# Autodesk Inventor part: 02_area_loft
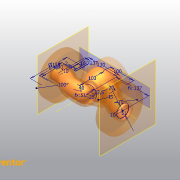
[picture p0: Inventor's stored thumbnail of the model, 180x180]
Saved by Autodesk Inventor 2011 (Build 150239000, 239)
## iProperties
Created: 2002-07
Part Number: 02_area_loft
Document SubType Name: Modeling
Designer: Lieven Grauls
Project: Valve Techcamp 2008
Density: 1 g/cm^3
Company: Autodesk
Control State: 0
Master: False
Checked Out: False
Shininess: 64.0
Length Units: 11269
Angle Units: 11279
Time Units: 11290
Mass Units: 11283
Length Display Precision: 3
Angle Display Precision: 2
Density: 0.0
Volumn: 0.0
Area: 0.0
PropertySet Name: Model Information
Author: Lieven Grauls
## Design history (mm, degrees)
sketch "Sketch2"
  geometry: L1 (-137, 0)-(-127, 0); L2 (137, 0)-(127, 0); L3 (45.866, 33.5)-(25.866, 33.5); L4 (-50, 103)-(50, 103); L5 (0, -142.6)-(0, 155.6) reference; L6 (-47.156, -25)-(0, -25); A1 r 100 centre (-127, -100) between (-69.969, -17.857) and (-127, 0); A2 r 40 centre (-47.156, 15) between (-69.969, -17.857) and (-47.156, -25); A3 r 70 centre (127, 70) between (77.614, 20.391) and (127, 0); A4 r 45 centre (45.866, -11.5) between (77.614, 20.391) and (45.866, 33.5); 4 further points
  constraints: 10 end point, 8 point on circle, 6 tangent, 4 centre point, 3 horizontal, 2 horizontal alignment, 2 perpendicular, 2 point on line, 1 midpoint, 1 other
  dimensions: "d8" = 137 distance of L1.start point (0, 0); "d9" = 100 radius of A1; "d10" = 40 radius of A2; "d15" = 137 distance of L2.start point (0, 0) (= d8); "d16" = 70 radius of A3; "d61" = 33.5 distance of the line from the sketch origin of L3; "d63" = 45 radius of A4; "d102" = 10 distance of L1.start L1.end; "d103" = 10 distance of L2.start L2.end; "d182" = 20 distance of L3.start L3.end; "d220" = 103 distance of the line from the sketch origin of L4; "d221" = 100 distance of L4.start L4.end; "d249" = 25 distance of the line from the sketch origin of L6
workplane "Work Plane6"
workplane "Work Plane2"
workplane "Work Plane1"
sketch "Sketch5"
  geometry: C1 r 25.5 at (0, 0); 1 further point
  constraints: 1 centre point, 1 coincident
  dimensions: "d24" = 51 diameter of C1
sketch "Sketch6"
  geometry: C1 r 25.5 at (0, 0); 1 further point
  constraints: 1 centre point, 1 coincident
  dimensions: "d25" = 51 diameter of C1
sketch "Sketch11"
  geometry: C1 r 25.5 at (0, 0); 1 further point
  constraints: 1 centre point, 1 coincident
  dimensions: "d104" = 51 diameter of C1 (= d24)
sketch "Sketch7"
  geometry: L1 (0, -22.6)-(0, 135.6) reference; L2 (-32.5, 103)-(-32.5, 74); L3 (-32.5, 74)-(-45.093, 69.417); L4 (-32.5, 8)-(0, 8); L5 (0, 103)-(-32.5, 103); L6 (-46.873, 22.579)-(-39.053, 11.411); L7 (-183.58, 0)-(30.597, 0) reference; A1 r 18 centre (-38.936, 52.502) between (-45.093, 69.417) and (-56.906, 51.462); A2 r 56 centre (-1, 54.699) between (-56.906, 51.462) and (-46.873, 22.579); A3 r 8 centre (-32.5, 16) between (-39.053, 11.411) and (-32.5, 8); 1 further point
  constraints: 10 end point, 6 point on circle, 5 point on line, 5 tangent, 3 centre point, 2 perpendicular, 1 horizontal, 1 parallel
  dimensions: "d28" = 65 diameter of L2 L1; "d30" = 110 deg angle of L2 L3; "d31" = 18 radius of A1; "d32" = 56 radius of A2; "d41" = 55 deg angle of L4 L6; "d65" = 8 radius of A3; "d135" = 103 distance between parallel lines of L7 L5; "d136" = 29 distance of L2.start L2.end; "d137" = 8 distance between parallel lines of L7 L4; "d138" = 1 distance from line of A2.centre L1; "d139" = 65 diameter of A3.centre L1
workplane "Work Plane5"
sketch "Sketch14"
  geometry: L1 (-102.1, 0)-(56.1, 0) reference; L2 (-15, -32)-(-15, 32); L3 (15, 25)-(15, -25); A1 r 56 centre (-12.302, 18.948) between (-9.774, -36.995) and (10.217, -32.325); A2 r 56 centre (-12.302, -18.948) between (10.217, 32.325) and (-9.774, 36.995); A3 r 5 centre (-10, 32) between (-9.774, 36.995) and (-15, 32); A4 r 5 centre (-10, -32) between (-15, -32) and (-9.774, -36.995); A5 r 8 centre (7, 25) between (15, 25) and (10.217, 32.325); A6 r 8 centre (7, -25) between (10.217, -32.325) and (15, -25); 2 further points
  constraints: 12 point on circle, 8 tangent, 6 centre point, 4 end point, 3 equal radius, 1 parallel, 1 perpendicular
  dimensions: "d144" = 15 distance from line of point (0, 0) L2 (= 0.5 x d145); "d145" = 30 distance between parallel lines of L2 L3; "d146" = 56 radius of A1; "d147" = 5 radius of A3; "d148" = 64 distance of A3.centre A4.centre; "d149" = 32 distance from line of L1 A4.centre (= 0.5 x d148); "d150" = 50 distance of A5.centre A6.centre; "d151" = 25 distance from line of L1 A6.centre (= 0.5 x d150); "d152" = 8 radius of A5
workplane "Work Plane10"
sketch "Sketch17"
  geometry: L1 (-9, 25.5)-(-15.5, 32); L2 (-15.5, 32)-(-16.5, 32); L3 (-9, 25.5)-(-9, 0); L4 (-88.753, 0)-(146.625, 0) reference; L5 (0, -7.725)-(0, 46.353) reference; A1 r 32 centre (-16.5, 0) between (-16.5, 32) and (-48.5, 0)
  constraints: 6 end point, 3 point on line, 2 perpendicular, 2 point on circle, 1 centre point, 1 tangent
  dimensions: "d250" = 32 radius of A1; "d252" = 45 deg angle of L3 L1; "d253" = 1 distance of L1.end L2.end; "d286" = 9 distance between parallel lines of L5 L3; "d287" = 25.5 distance from line of L4 L1.start
revolve "Revolution6" sketch "Sketch17" stored, may be unused: angle "d255" = 180 deg
sketch "Sketch19"
  geometry: L1 (32, 1)-(32, 0) reference; L2 (25.5, 7.5)-(32, 1) reference; L3 (-25.5, 7.5)-(25.5, 7.5) reference; L4 (-32, 1)-(-25.5, 7.5) reference; L5 (-32, 0)-(-32, 1) reference; A1 r 32 centre (0, 0) between (-32, 0) and (32, 0) reference; 1 further point
extrude "Extrusion4" join sketch "Sketch19" distance "d257" = 26; taper "d258" = 0 deg
fillet "Fillet11" dims "d259" = 8
extrude "Extrusion5" join sketch "Sketch11" stored distance "d260" = 30; taper "d261" = 0 deg
extrude "Extrusion2" join sketch "Sketch5" distance "d159" = 10; taper "d160" = 0 deg
loft "Loft4" dims "d262" = 10, "d263" = 90 deg, "d264" = 10, "d265" = 90 deg, "d266" = 0, "d267" = 90 deg, "d268" = 0, "d269" = 0, "d270" = 204.28206, "d271" = 10, "d272" = 114.64291, "d273" = 10, "d274" = 204.01489, "d275" = 10, "d276" = 67.31002, "d277" = 5.87128, "d278" = 204.2, "d279" = 9.94652, "d280" = 40.36207, "d281" = 3.52068, "d282" = 204.2, "d283" = 9.94591
  node "Edges4"
  node "Edges5"
extrude "Extrusion3" join sketch "Sketch6" distance "d183" = 10; taper "d184" = 0 deg
loft "Loft3" dims "d187" = 0, "d191" = 0, "d192" = 0, "d193" = 204.28206, "d194" = 10, "d195" = 110.06209, "d196" = 10, "d197" = 220, "d198" = 10.56486, "d199" = 55.03105, "d200" = 5, "d201" = 210, "d202" = 10.0143, "d207" = 10, "d208" = 90 deg, "d209" = 90 deg, "d213" = 0, "d214" = 90 deg
  node "Edges3"
feature "OffsetSrf1" dims "d203" = 8, "d204" = 8
feature "OffsetSrf2" dims "d205" = 8, "d206" = 8
revolve "Revolution5" stored, may be unused: angle "d212" = 90 deg
fillet "Fillet8" dims "d215" = 5
fillet "Fillet13" dims "d311" = 5
sketch "Sketch1"
  geometry: L1 (70, 103)-(70, 55); L2 (57.702, 15.997)-(40.477, -8.604); L3 (0, -42.404)-(0, 138.901) reference; L4 (28.19, -15)-(15, -15); L5 (-198.18, 0)-(118.199, 0) reference; L6 (-198.18, 103)-(118.199, 103) reference; A1 r 68 centre (2, 55) between (57.702, 15.997) and (70, 55); A2 r 15 centre (28.19, 0) between (28.19, -15) and (40.477, -8.604); 1 further point
  constraints: 6 end point, 4 point on circle, 4 tangent, 2 centre point, 1 perpendicular, 1 point on line
  dimensions: "d1" = 140 diameter of L1 L3; "d4" = 68 radius of A1; "d5" = 35 deg angle of L1 L2; "d217" = 15 distance between parallel lines of L4 L5; "d218" = 15 radius of A2; "d222" = 48 distance of L1.start L1.end; "d229" = 15 distance from line of L3 L4.end
feature "RevolutionSrf1" dims angle "d219" = 90 deg
sketch "Sketch8"
  geometry: L1 (-137, 85.5)-(-108, 85.5); L2 (-137, 85.5)-(-139.392, 17.012); L3 (-108, 85.5)-(-106.763, 14.622); L4 (-183.58, 0)-(30.597, 0) reference; L5 (-137, 135.6)-(-137, -22.6) reference
  constraints: 6 end point, 1 parallel, 1 point on line
  dimensions: "d47" = 29 distance of L1.start L1.end; "d223" = 92 deg angle of L4 L2; "d226" = 171 diameter of L1 L4; "d227" = 91 deg angle of L1 L3
feature "RevolutionSrf2" sketch "Sketch8" dims angle "d228" = 90 deg
mirror "Mirror1"
delete_face "Delete Face1"
sketch "Sketch15"
  geometry: L1 (-80, 100)-(-46.5, 100); L2 (-37.013, 96.7)-(-37.013, 60); L3 (-37.013, 60)-(-35.513, 60); L4 (-80, 113)-(-80, 100); L5 (-46.5, 100)-(-46.5, 96.7); L6 (-46.5, 96.7)-(-37.013, 96.7); L7 (0, -22.6)-(0, 135.6) reference; L8 (-183.58, 0)-(30.597, 0) reference; L9 (-35.513, 60)-(-35.513, 0); L10 (-35.513, 0)-(0, 0)
  constraints: 16 end point, 4 perpendicular, 2 vertical, 1 collinear, 1 horizontal, 1 parallel, 1 point on line
  dimensions: "d233" = 3.3 distance between parallel lines of L6 L1; "d237" = 100 distance between parallel lines of L1 L8; "d238" = 60 distance between parallel lines of L8 L3; "d239" = 93 diameter of L5 L7; "d240" = 74.025 diameter of L2 L7; "d241" = 71.025 diameter of L9 L7; "d242" = 160 diameter of L4 L7
sketch "Sketch20"
  geometry: L1 (-128, 77.5)-(-114, 77.5); L2 (-114, 77.5)-(-114, 45); L3 (-114, 45)-(-107, 45); L4 (-107, 45)-(-107, 100.638); L5 (-128, 77.5)-(-128, 48); L6 (-128, 48)-(-130, 48); L7 (-130, 48)-(-130, 0); L8 (0, -22.6)-(0, 135.6) reference; L9 (-183.58, 0)-(30.597, 0) reference; L10 (-130, 0)-(-152.983, 0)
  constraints: 16 end point, 4 parallel, 2 collinear, 2 perpendicular
  dimensions: "d290" = 16 distance between parallel lines of L2 L7; "d292" = 2 distance between parallel lines of L7 L5; "d306" = 155 diameter of L1 L9; "d307" = 96 diameter of L6 L9; "d308" = 90 diameter of L3 L9; "d309" = 130 distance between parallel lines of L8 L7; "d310" = 7 distance of L2.end L3.end
node "Flächen1"
node "Volumenkörpern"
node "Oberflächenkörpern"
node "Flächen2"
node "Flächen3"
node "Flächen4"
node "Flächen5"
node "Flächen6"
feature "RevolutionSrf3"
other parameters: "d285" = -5
